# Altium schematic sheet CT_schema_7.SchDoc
size 251 x 159 mm
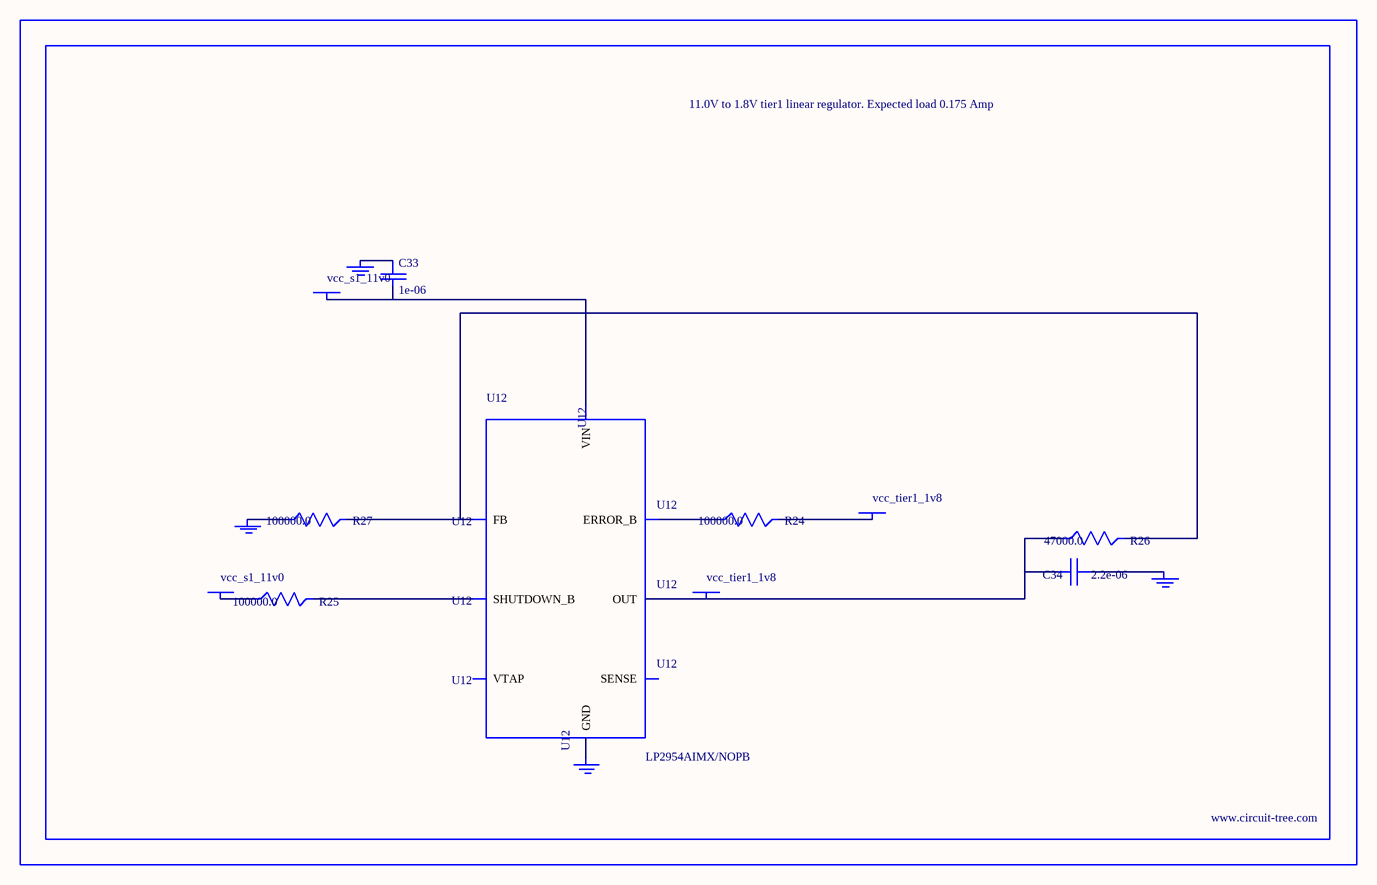
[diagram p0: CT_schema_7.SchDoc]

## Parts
BORDER6  (no value)
C33  1e-06  [EXV-9B]
C34  2.2e-06  [EXV-9B]
GND_INSTANCE_6_0  (no value)
GND_INSTANCE_6_1  (no value)
GND_INSTANCE_6_2  (no value)
GND_INSTANCE_6_3  (no value)
POWER_INSTANCE_6_0  vcc_s1_11v0
POWER_INSTANCE_6_1  vcc_tier1_1v8
POWER_INSTANCE_6_2  vcc_s1_11v0
POWER_INSTANCE_6_3  vcc_tier1_1v8
R24  100000.0  [R0603]
R25  100000.0  [R0603]
R26  47000.0  [R0603]
R27  100000.0  [R0603]
U12  LP2954AIMX/NOPB  [LP2954]

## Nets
NetC33_1: C33.1 GND_INSTANCE_6_2.0(GND)
NetC33_2: C33.2 POWER_INSTANCE_6_2.0(PWR) U12.8(VIN)
NetC34_1: C34.1 GND_INSTANCE_6_0.0(GND)
NetC34_2: C34.2 POWER_INSTANCE_6_3.0(PWR) R26.1 U12.1(OUT)
NetGND_INSTANCE_6_1_0: GND_INSTANCE_6_1.0(GND) R27.1
NetGND_INSTANCE_6_3_0: GND_INSTANCE_6_3.0(GND) U12.4(GND)
NetPOWER_INSTANCE_6_0_0: POWER_INSTANCE_6_0.0(PWR) R25.1
NetPOWER_INSTANCE_6_1_0: POWER_INSTANCE_6_1.0(PWR) R24.2
NetR24_1: R24.1 U12.5(ERROR_B)
NetR25_2: R25.2 U12.3(SHUTDOWN_B)
NetR26_2: R26.2 R27.2 U12.7(FB)

Not connected (* = marked no-connect by the designer): U12 2(SENSE) 6(VTAP)

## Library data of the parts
BORDER6 = BORDER_PAGE6
C33 = EDK105M050A9BAA
C34 = EDK225M050A9BAA
GND_INSTANCE_6_0-GND_INSTANCE_6_3 = GND
POWER_INSTANCE_6_0-POWER_INSTANCE_6_3 = PWR
R24 R25 R27 = RC0603JR-07100KL
R26 = RC0603JR-0747KL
